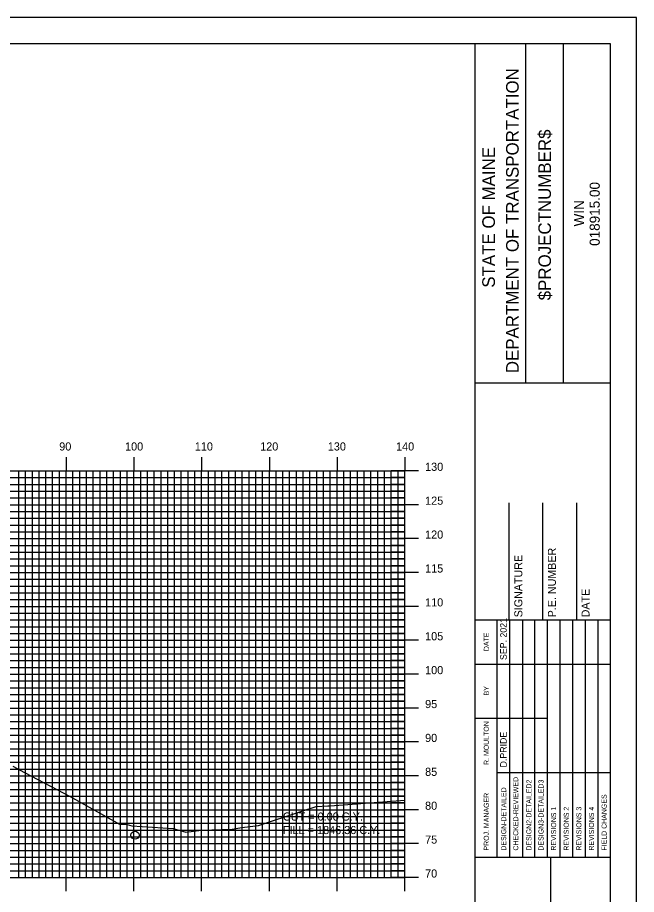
# Model space of a CAD drawing. Extents: x 856871 to 857214, y 364366 to 364586.
# Drawn here: x 857119.6 to 857211, y 364456.3 to 364585.7 of the extents above; entities that cross this region are included whole.
import ezdxf

# ---------------------------------------------------------------- set-up
doc = ezdxf.new("R2010")
doc.units = 0
for name, color, linetype in [('BORDER', 7, 'Continuous'), ('D_Text_Standard', 7, 'Continuous'), ('H_V ANNOTATION', 7, 'Continuous'), ('MAJOR', 7, 'Continuous'), ('MINOR', 7, 'Continuous'), ('PLOT BOUNDARY', 7, 'Continuous'), ('S_Drainage_Invert', 7, 'Continuous'), ('S_Roadway_Centerline', 7, 'Continuous')]:
    doc.layers.add(name, color=color, linetype=linetype)

msp = doc.modelspace()

# ---------------------------------------------------------------- linework, layer by layer
at = {"layer": 'BORDER'}
for p, q in [((857187.22, 364371.79), (857187.22, 364581.79)), ((857194.68, 364531.78), (857194.68, 364581.78)), ((857200.27, 364531.78), (857200.27, 364581.78)), ((857187.22, 364531.78), (857207.22, 364531.78)), ((857192.22, 364496.79), (857192.22, 364514.09)), ((857197.22, 364496.79), (857197.22, 364514.09)), ((857202.22, 364496.79), (857202.22, 364514.09)), ((857187.22, 364496.79), (857207.22, 364496.79)), ((857187.22, 364461.79), (857207.22, 364461.79)), ((857198.4, 364391.79), (857198.4, 364461.79))]:
    msp.add_line(p, q, dxfattribs=at)
msp.add_lwpolyline([(856887.22, 364371.79), (857207.22, 364371.79), (857207.22, 364581.79), (856887.22, 364581.79)], close=True, dxfattribs=at)
for points in [[(857190.45, 364490.29), (857190.45, 364496.79)], [(857192.32, 364461.8), (857192.32, 364496.79)], [(857194.18, 364496.79), (857194.18, 364461.8)], [(857196.04, 364461.8), (857196.04, 364496.79)], [(857197.91, 364461.8), (857197.91, 364496.79)], [(857199.77, 364461.8), (857199.77, 364496.79)], [(857201.63, 364461.8), (857201.63, 364496.79)], [(857203.5, 364461.8), (857203.5, 364496.79)], [(857205.36, 364461.8), (857205.36, 364496.79)], [(857190.45, 364461.8), (857190.45, 364495.38)], [(857187.22, 364490.29), (857207.22, 364490.29)], [(857187.22, 364482.29), (857190.45, 364482.29)], [(857190.45, 364482.29), (857197.91, 364482.29)], [(857190.45, 364474.29), (857207.22, 364474.29)]]:
    msp.add_lwpolyline(points, dxfattribs=at)
at = {"layer": 'MAJOR'}
for p, q in [((857126.82, 364520.79), (857126.82, 364518.79)), ((857136.82, 364520.79), (857136.82, 364518.79)), ((857146.82, 364520.79), (857146.82, 364518.79)), ((857156.82, 364520.79), (857156.82, 364518.79)), ((857166.82, 364520.79), (857166.82, 364518.79)), ((857176.82, 364520.79), (857176.82, 364518.79)), ((856896.82, 364518.79), (857176.82, 364518.79)), ((856896.82, 364518.79), (857176.82, 364518.79)), ((857126.82, 364458.79), (857126.82, 364518.79)), ((857136.82, 364458.79), (857136.82, 364518.79)), ((857146.82, 364458.79), (857146.82, 364518.79)), ((857156.82, 364458.79), (857156.82, 364518.79)), ((857166.82, 364458.79), (857166.82, 364518.79)), ((857178.83, 364518.79), (857174.82, 364518.79)), ((857176.82, 364458.79), (857176.82, 364518.79)), ((857176.82, 364458.79), (857176.82, 364518.79)), ((856896.82, 364513.79), (857176.82, 364513.79)), ((857178.83, 364513.79), (857174.82, 364513.79)), ((856896.82, 364508.79), (857176.82, 364508.79)), ((857178.83, 364508.79), (857174.82, 364508.79)), ((856896.82, 364503.79), (857176.82, 364503.79)), ((857178.83, 364503.79), (857174.82, 364503.79)), ((856896.82, 364498.79), (857176.82, 364498.79)), ((857178.83, 364498.79), (857174.82, 364498.79)), ((856896.82, 364493.79), (857176.82, 364493.79)), ((857178.83, 364493.79), (857174.82, 364493.79)), ((856896.82, 364488.79), (857176.82, 364488.79)), ((857178.83, 364488.79), (857174.82, 364488.79)), ((856896.82, 364483.79), (857176.82, 364483.79)), ((857178.83, 364483.79), (857174.82, 364483.79)), ((856896.82, 364478.79), (857176.82, 364478.79)), ((857178.83, 364478.79), (857174.82, 364478.79)), ((856896.82, 364473.79), (857176.82, 364473.79)), ((857178.83, 364473.79), (857174.82, 364473.79)), ((856896.82, 364468.79), (857176.82, 364468.79)), ((857178.83, 364468.79), (857174.82, 364468.79)), ((856896.82, 364463.79), (857176.82, 364463.79)), ((857178.83, 364463.79), (857174.82, 364463.79)), ((856896.82, 364458.79), (857176.82, 364458.79)), ((856896.82, 364458.79), (857176.82, 364458.79)), ((857126.82, 364456.78), (857126.82, 364458.79)), ((857136.82, 364456.78), (857136.82, 364458.79)), ((857146.82, 364456.78), (857146.82, 364458.79)), ((857156.82, 364456.78), (857156.82, 364458.79)), ((857166.82, 364456.78), (857166.82, 364458.79)), ((857178.83, 364458.79), (857174.82, 364458.79)), ((857176.82, 364456.78), (857176.82, 364458.79))]:
    msp.add_line(p, q, dxfattribs=at)
at = {"layer": 'MINOR'}
for p, q in [((857119.82, 364458.79), (857119.82, 364518.79)), ((857120.82, 364458.79), (857120.82, 364518.79)), ((857121.82, 364458.79), (857121.82, 364518.79)), ((857122.82, 364458.79), (857122.82, 364518.79)), ((857123.82, 364458.79), (857123.82, 364518.79)), ((857124.82, 364458.79), (857124.82, 364518.79)), ((857125.82, 364458.79), (857125.82, 364518.79)), ((857127.82, 364458.79), (857127.82, 364518.79)), ((857128.82, 364458.79), (857128.82, 364518.79)), ((857129.82, 364458.79), (857129.82, 364518.79)), ((857130.82, 364458.79), (857130.82, 364518.79)), ((857131.82, 364458.79), (857131.82, 364518.79)), ((857132.82, 364458.79), (857132.82, 364518.79)), ((857133.82, 364458.79), (857133.82, 364518.79)), ((857134.82, 364458.79), (857134.82, 364518.79)), ((857135.82, 364458.79), (857135.82, 364518.79)), ((857137.82, 364458.79), (857137.82, 364518.79)), ((857138.82, 364458.79), (857138.82, 364518.79)), ((857139.82, 364458.79), (857139.82, 364518.79)), ((857140.82, 364458.79), (857140.82, 364518.79)), ((857141.82, 364458.79), (857141.82, 364518.79)), ((857142.82, 364458.79), (857142.82, 364518.79)), ((857143.82, 364458.79), (857143.82, 364518.79)), ((857144.82, 364458.79), (857144.82, 364518.79)), ((857145.82, 364458.79), (857145.82, 364518.79)), ((857147.82, 364458.79), (857147.82, 364518.79)), ((857148.82, 364458.79), (857148.82, 364518.79)), ((857149.82, 364458.79), (857149.82, 364518.79)), ((857150.82, 364458.79), (857150.82, 364518.79)), ((857151.82, 364458.79), (857151.82, 364518.79)), ((857152.82, 364458.79), (857152.82, 364518.79)), ((857153.82, 364458.79), (857153.82, 364518.79)), ((857154.82, 364458.79), (857154.82, 364518.79)), ((857155.82, 364458.79), (857155.82, 364518.79)), ((857157.82, 364458.79), (857157.82, 364518.79)), ((857158.82, 364458.79), (857158.82, 364518.79)), ((857159.82, 364458.79), (857159.82, 364518.79)), ((857160.82, 364458.79), (857160.82, 364518.79)), ((857161.82, 364458.79), (857161.82, 364518.79)), ((857162.82, 364458.79), (857162.82, 364518.79)), ((857163.82, 364458.79), (857163.82, 364518.79)), ((857164.82, 364458.79), (857164.82, 364518.79)), ((857165.82, 364458.79), (857165.82, 364518.79)), ((857167.82, 364458.79), (857167.82, 364518.79)), ((857168.82, 364458.79), (857168.82, 364518.79)), ((857169.82, 364458.79), (857169.82, 364518.79)), ((857170.82, 364458.79), (857170.82, 364518.79)), ((857171.82, 364458.79), (857171.82, 364518.79)), ((857172.82, 364458.79), (857172.82, 364518.79)), ((857173.82, 364458.79), (857173.82, 364518.79)), ((857174.82, 364458.79), (857174.82, 364518.79)), ((857175.82, 364458.79), (857175.82, 364518.79)), ((856896.82, 364517.79), (857176.82, 364517.79)), ((857176.82, 364517.79), (857174.82, 364517.79)), ((856896.82, 364516.79), (857176.82, 364516.79)), ((857176.82, 364516.79), (857174.82, 364516.79)), ((856896.82, 364515.79), (857176.82, 364515.79)), ((856896.82, 364514.79), (857176.82, 364514.79)), ((857176.82, 364515.79), (857174.82, 364515.79)), ((857176.82, 364514.79), (857174.82, 364514.79)), ((856896.82, 364512.79), (857176.82, 364512.79)), ((857176.82, 364512.79), (857174.82, 364512.79)), ((856896.82, 364511.79), (857176.82, 364511.79)), ((857176.82, 364511.79), (857174.82, 364511.79)), ((856896.82, 364510.79), (857176.82, 364510.79)), ((856896.82, 364509.79), (857176.82, 364509.79)), ((857176.82, 364510.79), (857174.82, 364510.79)), ((857176.82, 364509.79), (857174.82, 364509.79)), ((856896.82, 364507.79), (857176.82, 364507.79)), ((857176.82, 364507.79), (857174.82, 364507.79)), ((856896.82, 364506.79), (857176.82, 364506.79)), ((856896.82, 364505.79), (857176.82, 364505.79)), ((857176.82, 364506.79), (857174.82, 364506.79)), ((857176.82, 364505.79), (857174.82, 364505.79)), ((856896.82, 364504.79), (857176.82, 364504.79)), ((857176.82, 364504.79), (857174.82, 364504.79)), ((856896.82, 364502.79), (857176.82, 364502.79)), ((856896.82, 364501.79), (857176.82, 364501.79)), ((857176.82, 364502.79), (857174.82, 364502.79)), ((857176.82, 364501.79), (857174.82, 364501.79)), ((856896.82, 364500.79), (857176.82, 364500.79)), ((857176.82, 364500.79), (857174.82, 364500.79)), ((856896.82, 364499.79), (857176.82, 364499.79)), ((857176.82, 364499.79), (857174.82, 364499.79)), ((856896.82, 364497.79), (857176.82, 364497.79)), ((856896.82, 364496.79), (857176.82, 364496.79)), ((857176.82, 364497.79), (857174.82, 364497.79)), ((857176.82, 364496.79), (857174.82, 364496.79)), ((856896.82, 364495.79), (857176.82, 364495.79)), ((857176.82, 364495.79), (857174.82, 364495.79)), ((856896.82, 364494.79), (857176.82, 364494.79)), ((857176.82, 364494.79), (857174.82, 364494.79)), ((856896.82, 364492.79), (857176.82, 364492.79)), ((857176.82, 364492.79), (857174.82, 364492.79)), ((856896.82, 364491.79), (857176.82, 364491.79)), ((857176.82, 364491.79), (857174.82, 364491.79)), ((856896.82, 364490.79), (857176.82, 364490.79)), ((857176.82, 364490.79), (857174.82, 364490.79)), ((856896.82, 364489.79), (857176.82, 364489.79)), ((857176.82, 364489.79), (857174.82, 364489.79)), ((856896.82, 364487.79), (857176.82, 364487.79)), ((857176.82, 364487.79), (857174.82, 364487.79)), ((856896.82, 364486.79), (857176.82, 364486.79)), ((857176.82, 364486.79), (857174.82, 364486.79)), ((856896.82, 364485.79), (857176.82, 364485.79)), ((857176.82, 364485.79), (857174.82, 364485.79)), ((856896.82, 364484.79), (857176.82, 364484.79)), ((857176.82, 364484.79), (857174.82, 364484.79)), ((856896.82, 364482.79), (857176.82, 364482.79)), ((857176.82, 364482.79), (857174.82, 364482.79)), ((856896.82, 364481.79), (857176.82, 364481.79)), ((857176.82, 364481.79), (857174.82, 364481.79)), ((856896.82, 364480.79), (857176.82, 364480.79)), ((856896.82, 364479.79), (857176.82, 364479.79)), ((857176.82, 364480.79), (857174.82, 364480.79)), ((857176.82, 364479.79), (857174.82, 364479.79)), ((856896.82, 364477.79), (857176.82, 364477.79)), ((857176.82, 364477.79), (857174.82, 364477.79)), ((856896.82, 364476.79), (857176.82, 364476.79)), ((857176.82, 364476.79), (857174.82, 364476.79)), ((856896.82, 364475.79), (857176.82, 364475.79)), ((856896.82, 364474.79), (857176.82, 364474.79)), ((857176.82, 364475.79), (857174.82, 364475.79)), ((857176.82, 364474.79), (857174.82, 364474.79)), ((856896.82, 364472.79), (857176.82, 364472.79)), ((857176.82, 364472.79), (857174.82, 364472.79)), ((856896.82, 364471.79), (857176.82, 364471.79)), ((856896.82, 364470.79), (857176.82, 364470.79)), ((857176.82, 364471.79), (857174.82, 364471.79)), ((857176.82, 364470.79), (857174.82, 364470.79)), ((856896.82, 364469.79), (857176.82, 364469.79)), ((857176.82, 364469.79), (857174.82, 364469.79)), ((856896.82, 364467.79), (857176.82, 364467.79)), ((857176.82, 364467.79), (857174.82, 364467.79)), ((856896.82, 364466.79), (857176.82, 364466.79)), ((856896.82, 364465.79), (857176.82, 364465.79)), ((857176.82, 364466.79), (857174.82, 364466.79)), ((857176.82, 364465.79), (857174.82, 364465.79)), ((856896.82, 364464.79), (857176.82, 364464.79)), ((857176.82, 364464.79), (857174.82, 364464.79)), ((856896.82, 364462.79), (857176.82, 364462.79)), ((856896.82, 364461.79), (857176.82, 364461.79)), ((857176.82, 364462.79), (857174.82, 364462.79)), ((857176.82, 364461.79), (857174.82, 364461.79)), ((856896.82, 364460.79), (857176.82, 364460.79)), ((857176.82, 364460.79), (857174.82, 364460.79)), ((856896.82, 364459.79), (857176.82, 364459.79)), ((857176.82, 364459.79), (857174.82, 364459.79))]:
    msp.add_line(p, q, dxfattribs=at)
at = {"layer": 'PLOT BOUNDARY'}
msp.add_lwpolyline([(856871.04, 364365.67), (857211.04, 364365.67), (857211.04, 364585.67), (856871.04, 364585.67)], close=True, dxfattribs=at)
at = {"layer": 'S_Drainage_Invert'}
msp.add_circle((857136.98, 364465.03), 0.6, dxfattribs=at)
msp.add_circle((857136.98, 364465.03), 0.6, dxfattribs=at)
at = {"layer": 'S_Roadway_Centerline'}
msp.add_lwpolyline([(857118.94, 364475.22), (857120.65, 364474.3), (857127.43, 364470.77), (857134.68, 364466.65), (857135.83, 364466.61), (857136.51, 364466.4), (857142.6, 364466.05), (857144.48, 364465.5), (857146.82, 364465.76), (857151.32, 364465.92), (857152.75, 364466.18), (857155.21, 364466.47), (857161.45, 364468.51), (857163.71, 364469.28), (857165.45, 364469.35), (857165.81, 364469.38), (857176.82, 364470.19)], dxfattribs=at)

# ---------------------------------------------------------------- texts
at = {"layer": 'BORDER'}
for s, height, p in [('DEPARTMENT OF TRANSPORTATION', 1.8635, (857193.64, 364533.2)), ('$PROJECTNUMBER$', 1.8635, (857198.41, 364543.95)), ('STATE OF MAINE', 1.8635, (857190.13, 364545.81)), ('018915.00', 1.491, (857205.61, 364551.98)), ('WIN', 1.491, (857203.3, 364554.85)), ('P.E. NUMBER', 1.1811, (857199.14, 364497.18)), ('SIGNATURE', 1.181, (857194.18, 364497.18)), ('DATE', 1.181, (857204.1, 364497.18)), ('SEP. 2021', 0.969, (857191.87, 364490.88)), ('DATE', 0.743, (857189.23, 364492.2)), ('BY', 0.743, (857189.23, 364485.66)), ('R. MOULTON', 0.745, (857189.23, 364475.4)), ('D.PRIDE', 0.969, (857191.87, 364475.04)), ('CHECKED-REVIEWED', 0.7455, (857193.58, 364462.77)), ('DESIGN2-DETAILED2', 0.7455, (857195.52, 364462.77)), ('DESIGN3-DETAILED3', 0.7455, (857197.31, 364462.77)), ('PROJ. MANAGER', 0.7455, (857189.23, 364462.77)), ('DESIGN-DETAILED', 0.7455, (857191.8, 364462.77)), ('FIELD CHANGES', 0.7455, (857206.63, 364462.77)), ('REVISIONS 1', 0.7455, (857199.17, 364462.77)), ('REVISIONS 2', 0.7455, (857201.04, 364462.77)), ('REVISIONS 3', 0.7455, (857202.9, 364462.77)), ('REVISIONS 4', 0.7455, (857204.76, 364462.77))]:
    msp.add_text(s, height=height, rotation=90, dxfattribs=at).set_placement(p)
at = {"layer": 'D_Text_Standard'}
for s, p in [('CUT = 0.00 C.Y.', (857158.82, 364467.19)), ('FILL = 1846.36 C.Y.', (857158.82, 364465.2))]:
    msp.add_text(s, height=1.2, dxfattribs=at).set_placement(p)
at = {"layer": 'H_V ANNOTATION'}
for s, p in [('90', (857125.79, 364521.79)), ('100', (857135.51, 364521.79)), ('110', (857145.81, 364521.79)), ('120', (857155.46, 364521.79)), ('130', (857165.45, 364521.79)), ('140', (857175.53, 364521.79)), ('130', (857179.82, 364518.79)), ('125', (857179.82, 364513.79)), ('120', (857179.82, 364508.79)), ('115', (857179.82, 364503.79)), ('110', (857179.82, 364498.79)), ('105', (857179.82, 364493.79)), ('100', (857179.82, 364488.79)), ('95', (857179.82, 364483.79)), ('90', (857179.82, 364478.79)), ('85', (857179.82, 364473.79)), ('80', (857179.82, 364468.79)), ('75', (857179.82, 364463.79)), ('70', (857179.82, 364458.79))]:
    msp.add_text(s, height=1.2, dxfattribs=at).set_placement(p)

doc.saveas('drawing.dxf')
